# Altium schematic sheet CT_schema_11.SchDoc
size 278 x 170 mm
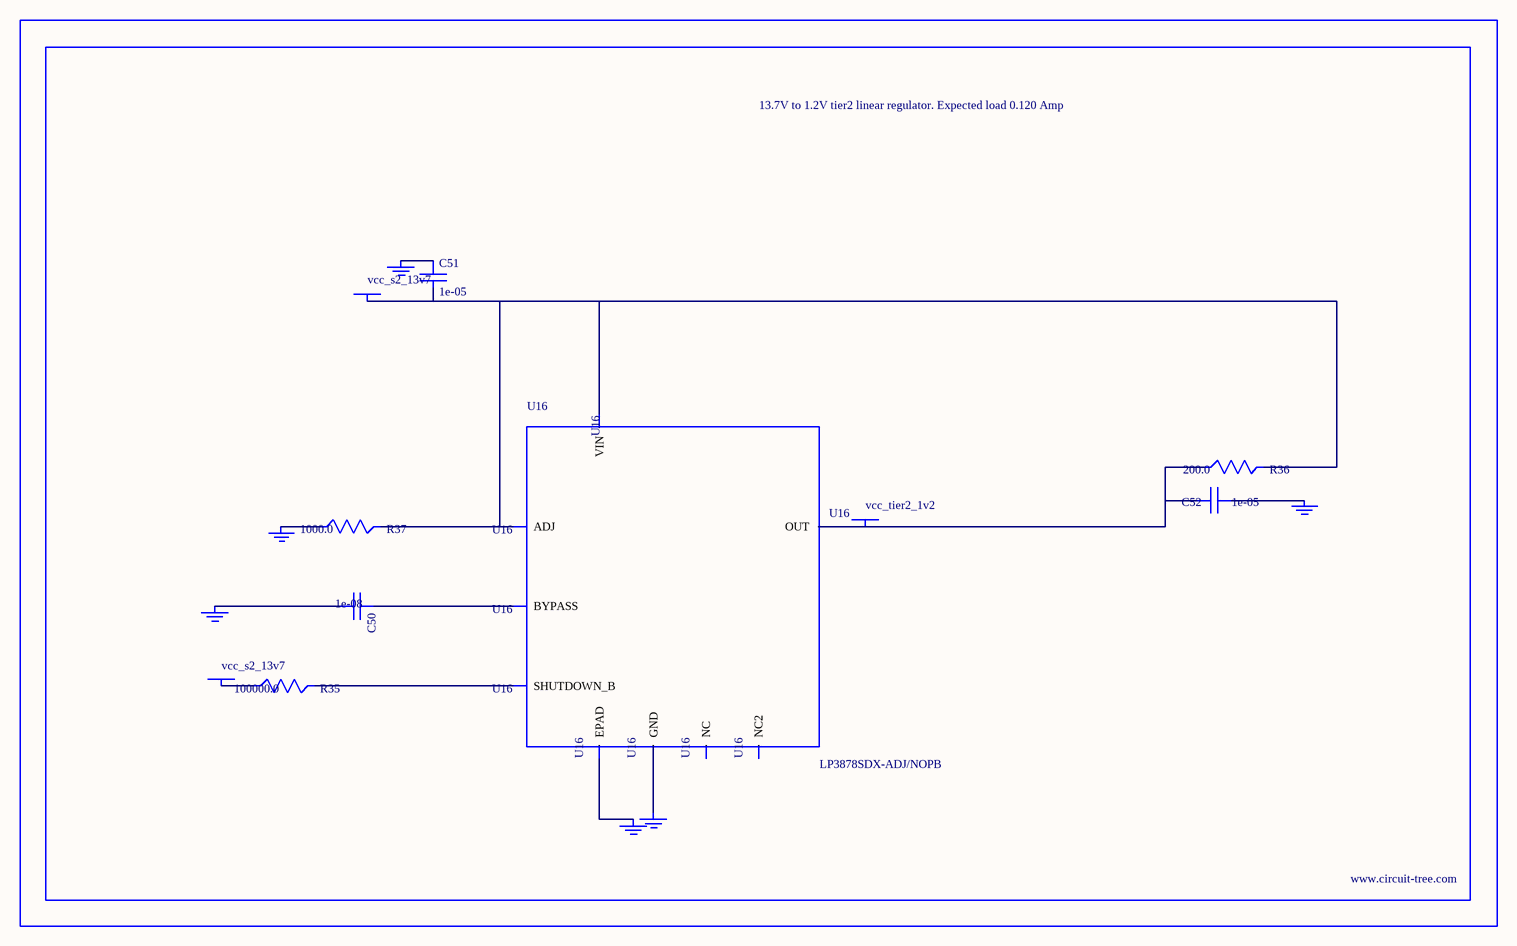
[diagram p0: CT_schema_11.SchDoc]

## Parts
BORDER10  (no value)
C50  1e-08  [C0402]
C51  1e-05  [C1210]
C52  1e-05  [C0805]
GND_INSTANCE_10_0  (no value)
GND_INSTANCE_10_1  (no value)
GND_INSTANCE_10_2  (no value)
GND_INSTANCE_10_3  (no value)
GND_INSTANCE_10_4  (no value)
GND_INSTANCE_10_5  (no value)
POWER_INSTANCE_10_0  vcc_s2_13v7
POWER_INSTANCE_10_1  vcc_s2_13v7
POWER_INSTANCE_10_2  vcc_tier2_1v2
R35  100000.0  [R0603]
R36  200.0  [R0603]
R37  1000.0  [R0603]
U16  LP3878SDX-ADJ/NOPB  [WSON-8]

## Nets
NetC50_1: C50.1 U16.1(BYPASS)
NetC50_2: C50.2 GND_INSTANCE_10_0.0(GND)
NetC51_1: C51.1 GND_INSTANCE_10_1.0(GND)
NetC51_2: C51.2 POWER_INSTANCE_10_0.0(PWR) R36.2 R37.2 U16.4(VIN) U16.6(ADJ)
NetC52_1: C52.1 GND_INSTANCE_10_2.0(GND)
NetC52_2: C52.2 POWER_INSTANCE_10_2.0(PWR) R36.1 U16.5(OUT)
NetGND_INSTANCE_10_3_0: GND_INSTANCE_10_3.0(GND) R37.1
NetGND_INSTANCE_10_4_0: GND_INSTANCE_10_4.0(GND) U16.PAD(EPAD)
NetGND_INSTANCE_10_5_0: GND_INSTANCE_10_5.0(GND) U16.3(GND)
NetPOWER_INSTANCE_10_1_0: POWER_INSTANCE_10_1.0(PWR) R35.1
NetR35_2: R35.2 U16.8(SHUTDOWN_B)

Not connected (* = marked no-connect by the designer): U16 2(NC) 7(NC2)

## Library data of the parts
BORDER10 = BORDER_PAGE10
C50 = C0402C103K3RAC
C51 = C1210C106K5PACTU
C52 = GRM219R60J106ME19D
GND_INSTANCE_10_0-GND_INSTANCE_10_5 = GND
POWER_INSTANCE_10_0-POWER_INSTANCE_10_2 = PWR
R35 = RC0603JR-07100KL
R36 = RC0603JR-07200RL
R37 = RC0603JR-071KL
